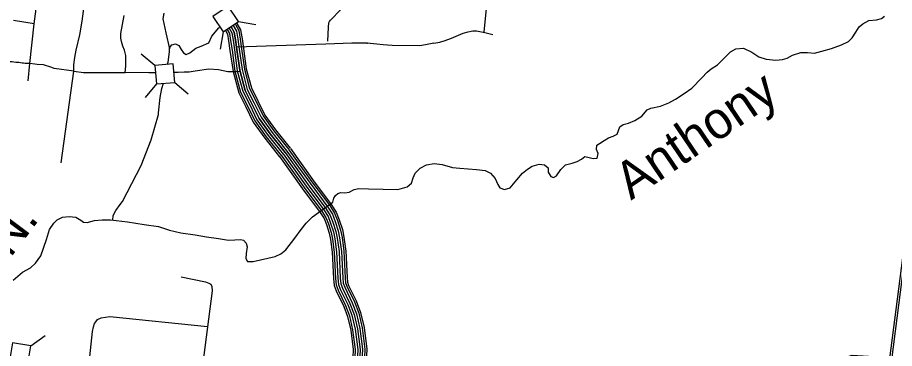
# Model space of a CAD drawing. Extents: x 1788175 to 1969470, y 584502 to 738744.
# Drawn here: x 1823147 to 1834430, y 650019 to 654272 of the extents above; entities that cross this region are included whole.
import ezdxf

# ---------------------------------------------------------------- set-up
doc = ezdxf.new("R2010")
doc.units = 0
for name, color, linetype in [('DESIGN - DRAINAGE - Bridges and Cross Drains Size Text', 7, 'Continuous'), ('DESIGN - TRANSPORTATION - Text', 7, 'Continuous'), ('SURVEY - CONTOURS - Index with Text', 7, 'Continuous'), ('SURVEY - DRAINAGE - Storm Sewer', 7, 'Continuous'), ('SURVEY - TRANSPORTATION - Roads', 7, 'Continuous')]:
    doc.layers.add(name, color=color, linetype=linetype)

msp = doc.modelspace()

# ---------------------------------------------------------------- linework, layer by layer
at = {"layer": 'DESIGN - TRANSPORTATION - Text'}
for points in [[(1825030, 654329), (1825015, 654255), (1825056, 654074), (1825102, 653868)], [(1830616, 652525), (1830595, 652574), (1830598, 652632), (1830633, 652653), (1830693, 652690), (1830750, 652725), (1830812, 652746), (1830862, 652774), (1830877, 652821), (1830896, 652865), (1830940, 652896), (1831009, 652913), (1831089, 652950), (1831180, 653005), (1831249, 653086), (1831295, 653107), (1831418, 653133), (1831526, 653177), (1831613, 653224), (1831722, 653294), (1831823, 653362), (1831949, 653498), (1832020, 653571), (1832073, 653612), (1832154, 653663), (1832249, 653760), (1832318, 653829), (1832387, 653869), (1832489, 653878), (1832596, 653826), (1832683, 653768), (1832780, 653735), (1832902, 653725), (1832988, 653733), (1833048, 653750), (1833117, 653787), (1833227, 653821), (1833309, 653824), (1833399, 653816), (1833495, 653839), (1833620, 653875), (1833749, 653919), (1833837, 653965), (1833884, 654013), (1833933, 654082), (1833976, 654151), (1834021, 654191), (1834099, 654233), (1834198, 654244), (1834262, 654261), (1834303, 654290)], [(1825078, 653670), (1825083, 653697), (1825100, 653831), (1825102, 653883), (1825133, 653920), (1825179, 653934), (1825223, 653911), (1825250, 653860), (1825281, 653818), (1825315, 653795), (1825363, 653818), (1825440, 653877), (1825510, 653904), (1825607, 653946), (1825647, 654034), (1825737, 654138), (1825756, 654146)], [(1824495, 651909), (1824736, 652369), (1824864, 652699), (1824959, 653024), (1824959, 653046), (1824980, 653246), (1825004, 653358), (1825026, 653427)], [(1830503, 652473), (1830555, 652458), (1830603, 652463), (1830616, 652525)], [(1823090, 650895), (1823149, 650949), (1823212, 651000), (1823314, 651054), (1823377, 651113), (1823445, 651210), (1823519, 651418), (1823559, 651547), (1823614, 651628), (1823657, 651672), (1823725, 651705), (1823810, 651716), (1823898, 651704), (1823959, 651668), (1823995, 651643), (1824043, 651636), (1824137, 651663), (1824236, 651672), (1824342, 651672), (1824562, 651647), (1824776, 651614), (1824962, 651586), (1825103, 651538), (1825247, 651506), (1825431, 651479), (1825579, 651455), (1825731, 651431), (1825859, 651409), (1825943, 651414), (1826017, 651421), (1826053, 651410), (1826087, 651374), (1826100, 651326), (1826089, 651238), (1826086, 651176), (1826104, 651135), (1826180, 651136), (1826463, 651202), (1826535, 651233), (1826600, 651287), (1826716, 651437), (1826798, 651548), (1826861, 651629), (1826942, 651710), (1827203, 651898), (1827216, 651952), (1827238, 651986), (1827266, 652012), (1827305, 652023), (1827357, 652020), (1827415, 652029), (1827479, 652061), (1827538, 652074), (1827662, 652070), (1828040, 652063), (1828159, 652097), (1828216, 652144), (1828236, 652210), (1828261, 652272), (1828326, 652337), (1828407, 652378), (1828507, 652398), (1828611, 652385), (1828745, 652345), (1828839, 652336), (1829053, 652319), (1829165, 652305), (1829233, 652270), (1829294, 652203), (1829327, 652125), (1829354, 652081), (1829414, 652062), (1829483, 652083), (1829572, 652186), (1829643, 652271), (1829706, 652322), (1829769, 652363), (1829857, 652386), (1829927, 652379), (1829973, 652342), (1829976, 652284), (1830009, 652229), (1830041, 652215), (1830080, 652238), (1830137, 652320), (1830196, 652377), (1830282, 652400), (1830346, 652423), (1830403, 652450), (1830445, 652485), (1830503, 652473)], [(1824371, 651669), (1824379, 651728), (1824411, 651791), (1824466, 651869), (1824495, 651909)]]:
    msp.add_lwpolyline(points, dxfattribs=at)
at = {"layer": 'SURVEY - CONTOURS - Index with Text'}
for points in [[(1833548, 648623), (1833568, 648712), (1833617, 648884), (1833661, 649175), (1833749, 649768), (1833762, 649816), (1833778, 649856), (1833808, 649906), (1833886, 649931), (1834094, 649921), (1834371, 649891), (1834619, 651815), (1834704, 652517)], [(1833572, 648618), (1833592, 648706), (1833641, 648878), (1833685, 649171), (1833774, 649763), (1833785, 649808), (1833800, 649845), (1833824, 649885), (1833889, 649906), (1834092, 649896), (1834376, 649866), (1834391, 649864), (1834394, 649872), (1834644, 651812), (1834728, 652515)]]:
    msp.add_lwpolyline(points, dxfattribs=at)
at = {"layer": 'SURVEY - DRAINAGE - Storm Sewer'}
for p, q in [((1825990, 654223), (1826214, 654181)), ((1825794, 654089), (1825752, 653866)), ((1824913, 653656), (1824739, 653802)), ((1824933, 653419), (1824787, 653245)), ((1825170, 653439), (1825343, 653293)), ((1823318, 650054), (1823502, 650187))]:
    msp.add_line(p, q, dxfattribs=at)
for points in [[(1825660, 654285), (1825794, 654089), (1825990, 654223), (1825856, 654419)], [(1824933, 653419), (1825170, 653439), (1825149, 653676), (1824913, 653656)], [(1823318, 650054), (1823083, 650092), (1823045, 649858), (1823280, 649820)]]:
    msp.add_lwpolyline(points, close=True, dxfattribs=at)
at = {"layer": 'SURVEY - TRANSPORTATION - Roads'}
for points in [[(1827147, 654149), (1827153, 654203), (1827159, 654222), (1827172, 654240), (1827571, 654653), (1827890, 654995), (1828079, 655122), (1828176, 655192), (1828443, 655457), (1828518, 655514), (1828826, 655777)], [(1823872, 653581), (1823873, 653666), (1823882, 653758), (1823899, 653852), (1823946, 654051), (1823977, 654224), (1824002, 654417), (1824044, 654732), (1824050, 654751), (1824056, 654776), (1824053, 654804), (1824048, 654833), (1824041, 654861), (1824031, 654888), (1824020, 654914), (1824009, 654941), (1824001, 654971), (1823999, 655002), (1824001, 655035), (1824006, 655066), (1824010, 655096), (1824014, 655118), (1824016, 655137), (1824019, 655164)], [(1829249, 655081), (1829209, 654737), (1829145, 654084)], [(1823359, 654192), (1823424, 654675)], [(1823359, 654192), (1823096, 654235)], [(1823304, 653681), (1823359, 654192)], [(1824533, 653566), (1824538, 653648), (1824539, 653784), (1824523, 653851), (1824500, 653904), (1824484, 653965), (1824475, 654007), (1824477, 654065), (1824518, 654298)], [(1825944, 654191), (1825949, 654184), (1825992, 654106), (1826011, 653996), (1826029, 653871), (1826066, 653608), (1826133, 653358), (1826217, 653192), (1826308, 653007), (1826446, 652814), (1826636, 652575)], [(1825965, 654205), (1825970, 654197), (1826016, 654114), (1826035, 654000), (1826053, 653875), (1826090, 653613), (1826156, 653367), (1826239, 653203), (1826329, 653019), (1826466, 652828), (1826656, 652591)], [(1825821, 654107), (1825821, 654106), (1825849, 654056), (1825863, 653973), (1825880, 653850), (1825919, 653578), (1825992, 653304), (1826083, 653125), (1826179, 652929), (1826327, 652723), (1826519, 652482)], [(1825842, 654121), (1825843, 654119), (1825874, 654065), (1825888, 653977), (1825906, 653854), (1825944, 653583), (1826016, 653314), (1826106, 653137), (1826201, 652943), (1826347, 652739), (1826539, 652498)], [(1825867, 654139), (1825870, 654136), (1825903, 654075), (1825919, 653982), (1825937, 653858), (1825974, 653589), (1826045, 653325), (1826134, 653151), (1826227, 652959), (1826372, 652757), (1826564, 652517)], [(1825893, 654156), (1825896, 654152), (1825933, 654085), (1825949, 653987), (1825967, 653862), (1826005, 653595), (1826074, 653336), (1826161, 653164), (1826254, 652975), (1826397, 652776), (1826588, 652537)], [(1826588, 652537), (1826397, 652776), (1826254, 652975), (1826161, 653164), (1826074, 653336), (1826005, 653595), (1825967, 653862), (1825949, 653987), (1825933, 654085), (1825896, 654152), (1825893, 654156)], [(1825919, 654174), (1825923, 654168), (1825963, 654096), (1825980, 653992), (1825998, 653867), (1826035, 653602), (1826103, 653347), (1826189, 653178), (1826281, 652991), (1826421, 652795), (1826612, 652556)], [(1827137, 653970), (1827147, 654149)], [(1828505, 653942), (1828582, 653956), (1828649, 653975), (1828731, 654006), (1828791, 654033), (1828881, 654069), (1828944, 654086), (1828983, 654097), (1829006, 654103), (1829051, 654103), (1829158, 654080), (1829264, 654052)], [(1828505, 653942), (1828395, 653922), (1828322, 653910), (1827966, 653914), (1827905, 653917), (1827850, 653921), (1827771, 653930), (1827641, 653941), (1827648, 653941), (1827581, 653942), (1827446, 653941), (1827114, 653930), (1825963, 653892)], [(1823304, 653681), (1823243, 653683), (1823224, 653685), (1823205, 653687), (1823185, 653690), (1823164, 653692), (1823144, 653694), (1823123, 653696), (1823101, 653699), (1823078, 653702), (1823053, 653704), (1823028, 653707), (1823002, 653710), (1822977, 653713), (1822953, 653715), (1822930, 653718), (1822908, 653720), (1822889, 653722), (1822873, 653723), (1822860, 653724), (1822850, 653725), (1822808, 653729)], [(1823282, 653458), (1823304, 653681)], [(1823872, 653581), (1823618, 653617), (1823588, 653630), (1823479, 653663), (1823398, 653670), (1823370, 653673), (1823304, 653681)], [(1823709, 652406), (1823872, 653581)], [(1823872, 653581), (1823994, 653567), (1824143, 653567), (1824533, 653566)], [(1824921, 653562), (1824835, 653561), (1824533, 653566)], [(1826008, 653577), (1825963, 653572), (1825853, 653574), (1825731, 653601), (1825608, 653609), (1825434, 653582), (1825353, 653571), (1825291, 653570), (1825215, 653567), (1825159, 653565)], [(1826537, 652501), (1826835, 652086), (1827061, 651783), (1827114, 651701), (1827146, 651621), (1827182, 651508), (1827200, 651424), (1827221, 651257), (1827238, 650919), (1827245, 650836), (1827270, 650769), (1827366, 650571), (1827418, 650436), (1827458, 650260), (1827492, 650005), (1827477, 649694), (1827467, 649521)], [(1826563, 652519), (1826860, 652105), (1827087, 651801), (1827142, 651715), (1827175, 651631), (1827212, 651516), (1827230, 651429), (1827252, 651260), (1827268, 650921), (1827276, 650842), (1827298, 650782), (1827395, 650583), (1827447, 650445), (1827489, 650265), (1827524, 650006), (1827508, 649693), (1827498, 649519)], [(1826588, 652537), (1826885, 652123), (1827112, 651818), (1827169, 651729), (1827204, 651642), (1827242, 651524), (1827261, 651435), (1827283, 651263), (1827299, 650923), (1827306, 650849), (1827327, 650794), (1827423, 650595), (1827477, 650454), (1827519, 650271), (1827555, 650007), (1827539, 649691), (1827529, 649518)], [(1826588, 652537), (1826885, 652123), (1827112, 651818), (1827169, 651729), (1827204, 651642), (1827242, 651524), (1827261, 651435), (1827283, 651263), (1827299, 650923), (1827306, 650849), (1827327, 650794), (1827423, 650595), (1827477, 650454), (1827519, 650271), (1827555, 650007), (1827539, 649691), (1827529, 649518)], [(1826613, 652555), (1826910, 652141), (1827138, 651836), (1827197, 651743), (1827234, 651652), (1827272, 651532), (1827291, 651440), (1827314, 651266), (1827330, 650926), (1827337, 650856), (1827356, 650806), (1827452, 650607), (1827507, 650463), (1827550, 650276), (1827586, 650009), (1827570, 649689), (1827560, 649516)], [(1826638, 652573), (1826935, 652160), (1827163, 651854), (1827225, 651758), (1827263, 651663), (1827302, 651540), (1827322, 651445), (1827345, 651268), (1827361, 650928), (1827367, 650863), (1827384, 650818), (1827480, 650620), (1827537, 650472), (1827580, 650282), (1827617, 650010), (1827601, 649688), (1827591, 649514)], [(1826658, 652587), (1826955, 652174), (1827184, 651868), (1827247, 651769), (1827286, 651671), (1827326, 651547), (1827346, 651449), (1827370, 651271), (1827386, 650929), (1827392, 650869), (1827407, 650828), (1827503, 650630), (1827560, 650479), (1827605, 650286), (1827642, 650011), (1827625, 649686), (1827615, 649513)], [(1826517, 652486), (1826814, 652071), (1827040, 651768), (1827091, 651689), (1827122, 651612), (1827157, 651502), (1827174, 651420), (1827196, 651255), (1827212, 650917), (1827220, 650830), (1827246, 650759), (1827343, 650560), (1827393, 650428), (1827433, 650255), (1827467, 650004), (1827451, 649696), (1827441, 649523)], [(1825250, 650941), (1825563, 650873), (1825607, 650860), (1825633, 650844), (1825645, 650816), (1825650, 650760), (1825510, 649665)], [(1824067, 649829), (1824113, 650237), (1824122, 650297), (1824138, 650341), (1824153, 650362), (1824175, 650390), (1824222, 650413), (1824336, 650430), (1825592, 650303)]]:
    msp.add_lwpolyline(points, dxfattribs=at)

# ---------------------------------------------------------------- texts
at = {"layer": 'DESIGN - DRAINAGE - Bridges and Cross Drains Size Text'}
for s, rotation, p in [('Anthony', 34.194, (1831040, 651918)), ('N.', 53.0923, (1823054, 651175))]:
    msp.add_text(s, height=475, rotation=rotation, dxfattribs=at).set_placement(p)

doc.saveas('drawing.dxf')
